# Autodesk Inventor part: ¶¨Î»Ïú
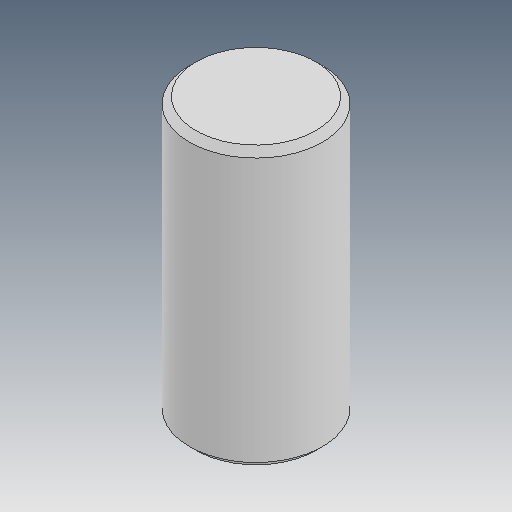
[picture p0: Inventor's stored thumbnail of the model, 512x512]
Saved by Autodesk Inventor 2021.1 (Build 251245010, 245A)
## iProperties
Created: 2019-04
Part Number: ¶¨Î»Ïú
Material: Ogólny
Document SubType Name: Modeling
Designer: user
Density: 1 g/cm^3
Appearance: Domyślna
Author: user
Revision Number: ÈÎºÎ
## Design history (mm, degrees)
feature "Ðý×ª1"
node "Bryła1"
